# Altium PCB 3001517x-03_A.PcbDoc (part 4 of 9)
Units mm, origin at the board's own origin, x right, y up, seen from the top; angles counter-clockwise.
Board outline 100 x 72 mm, 10 copper layers (Top, GND_2, Signal_3, Signal_4, PWR_5, GND_6, Signal_7, Signal_8, GND_9, Bottom), stack 1.6 mm thick; 602 components, 497 nets, 2372 pads, 1602 vias.
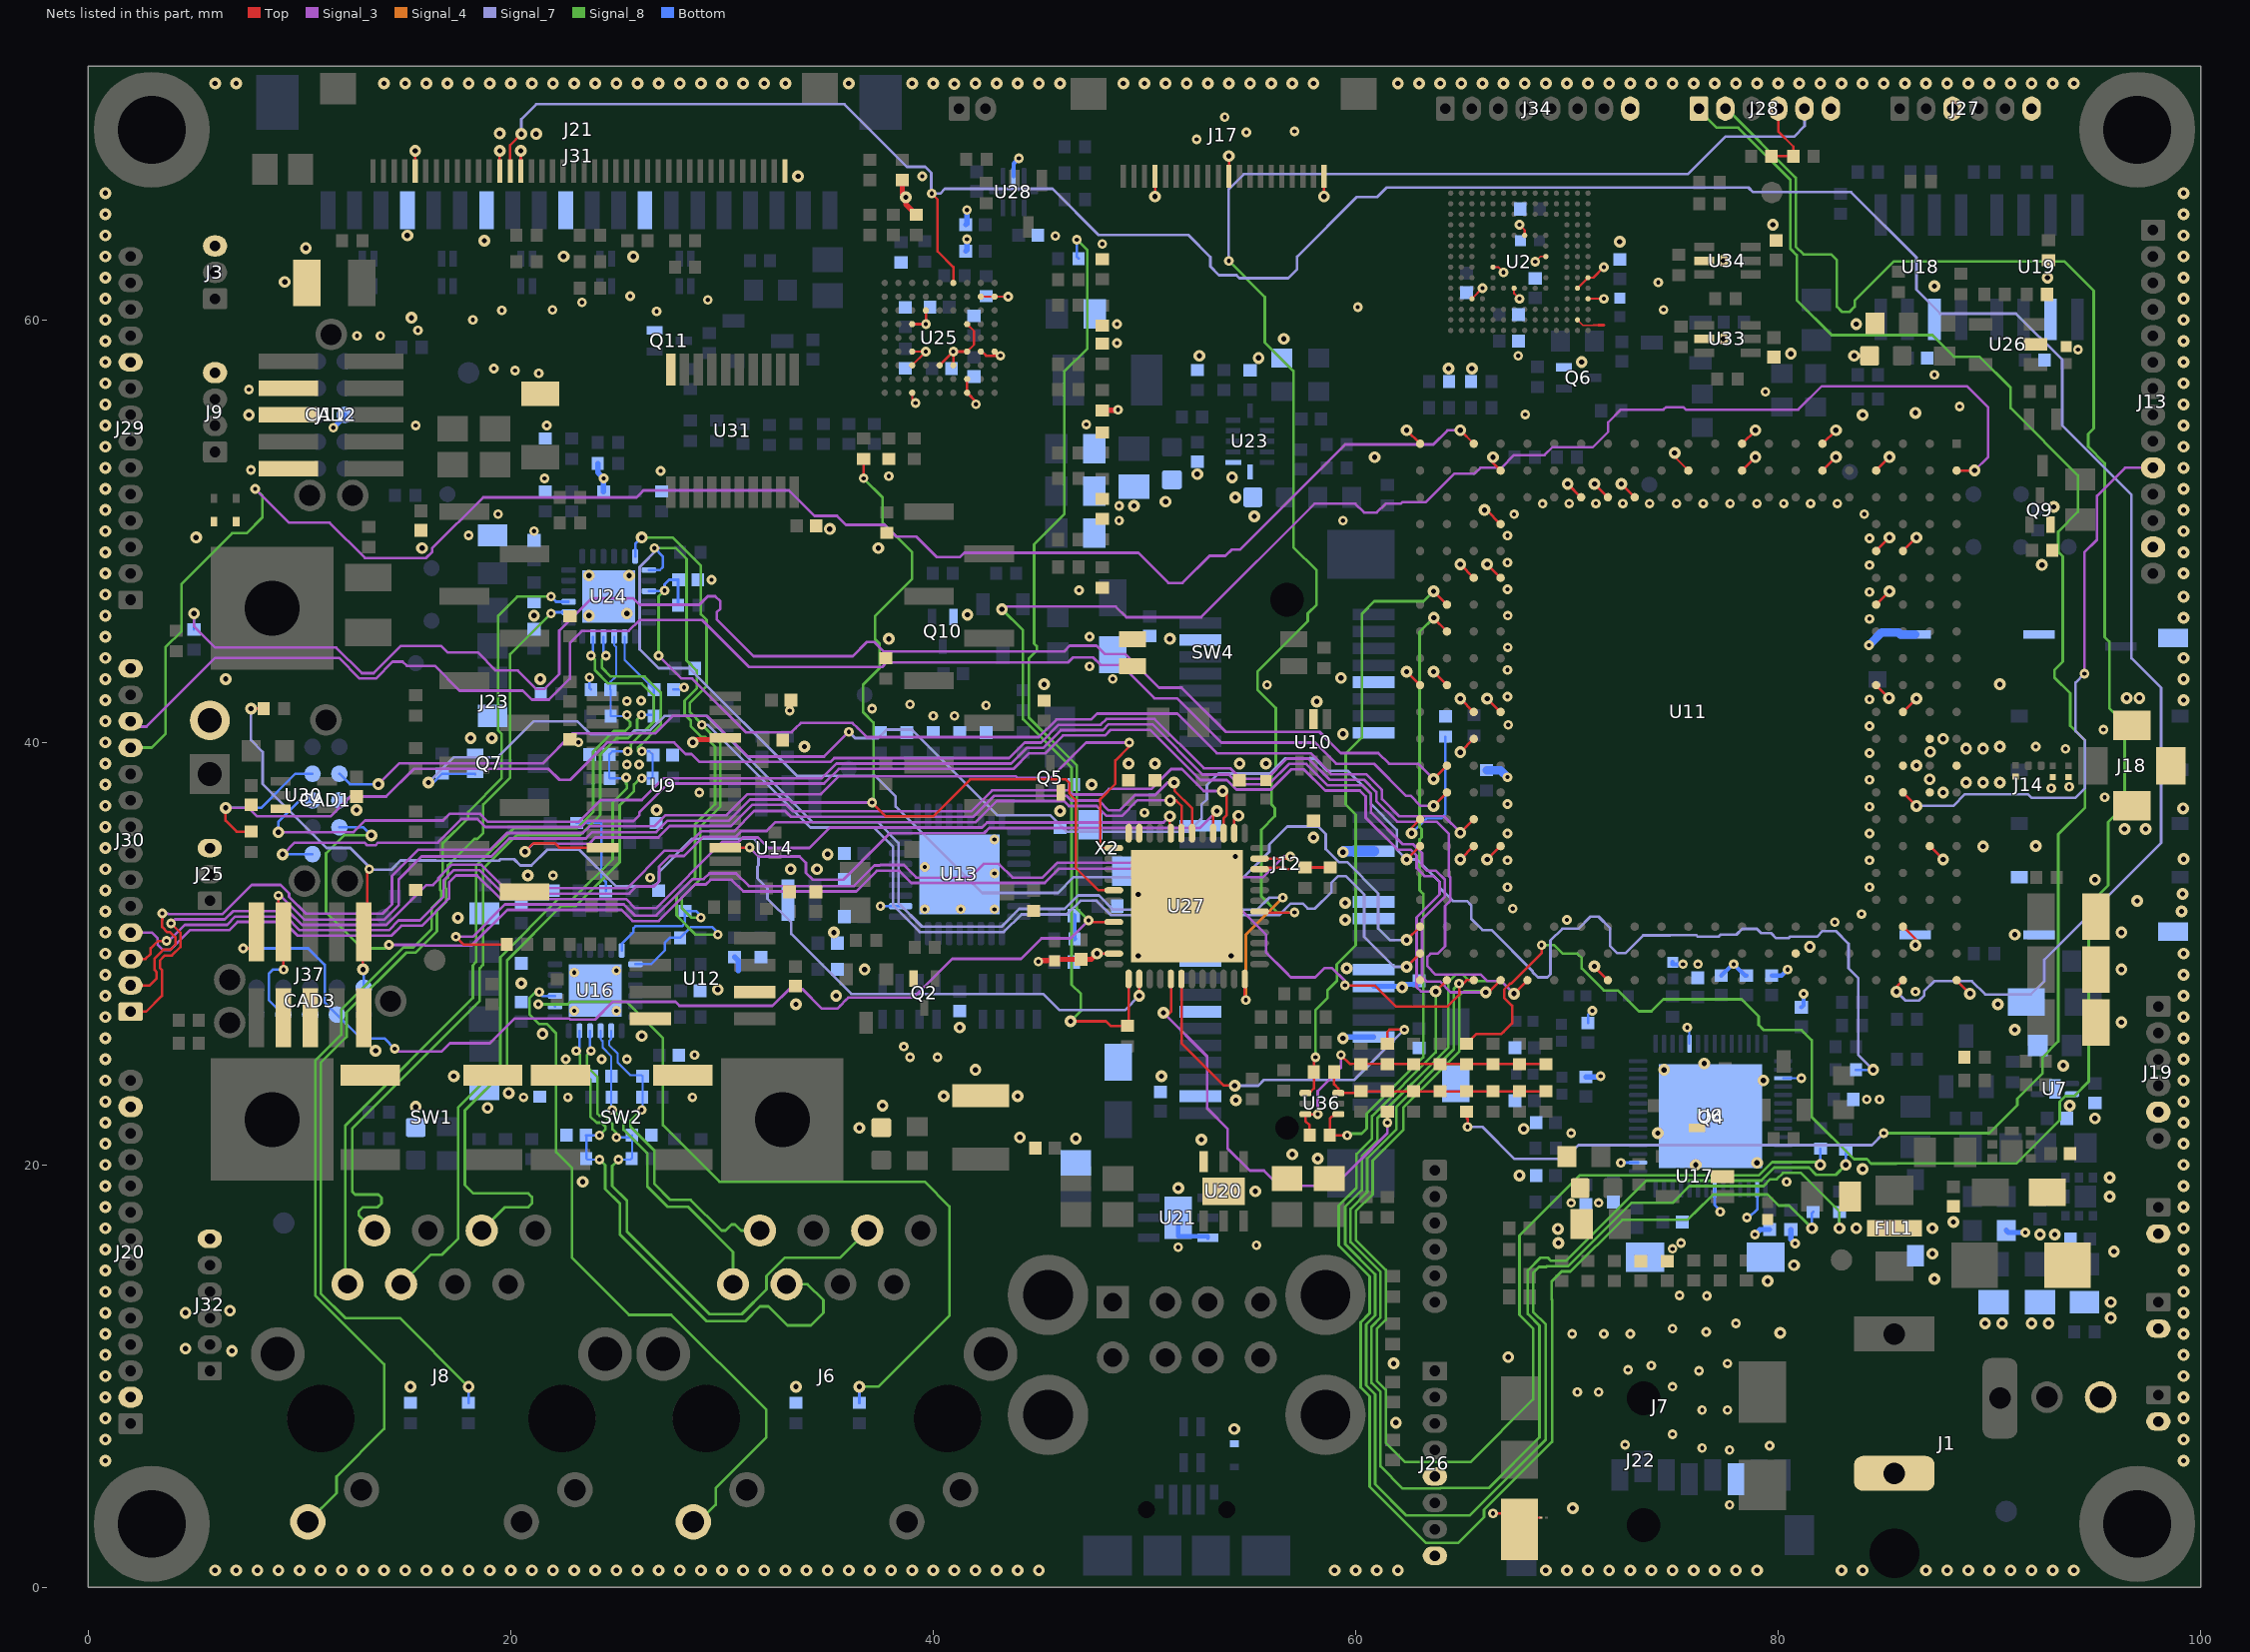
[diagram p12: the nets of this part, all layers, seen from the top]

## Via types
v1: diameter 0.56, hole 0.25, Top to Bottom, tented both sides, 1002 vias
v2: diameter 0.46, hole 0.2, Top to Bottom, tented both sides, 468 vias
v3: diameter 0.457, hole 0.2, Top to Bottom, tented both sides, 132 vias

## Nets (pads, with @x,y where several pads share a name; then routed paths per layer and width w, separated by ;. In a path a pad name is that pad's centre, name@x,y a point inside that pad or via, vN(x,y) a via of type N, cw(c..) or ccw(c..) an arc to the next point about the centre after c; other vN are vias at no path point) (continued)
ENET_MDC: R50.2 U11.AA19 U16.13 U24.13 | length 82.7
  Top w0.119: v1(62.415,30.645) U11.AA19@63.05,31.28
  Signal_8 w0.127: v2(26.8,49.2) 27.8,49.2 28.32,48.68 28.32,43.88 28.8,43.4 28.8,42.554 28.225,41.979 28.225,41.317 28.525,41.018 28.525,40.755 29.03,40.25 29.215,40.25 29.67,39.795 29.67,37.076 28.72,36.126 28.72,33.634 27.846,32.759 27.846,31.809 28.755,30.9 29.9,30.9 v2(29.8,30.9)
  Signal_7 w0.127: v2(26.8,49.2) 27,49.2 26.1,48.3 26.1,44.405 26.995,43.51 28.447,43.51 33.535,38.422 37.243,38.422 38.221,37.445 38.221,36.966 42.315,32.872 43.285,32.872 43.287,32.874 45.902,32.874 46.649,33.621 54.705,33.621 55.908,34.824 55.908,35.158 56.768,36.017 58.223,36.017 58.585,35.656 58.585,34.95 59.205,34.329 59.589,34.329 61.067,32.851 61.067,31.19 61.613,30.645 v1(62.415,30.645)
  Bottom w0.119: U16.13@25.9,29.5 26.633,29.5 27.3,30.167 27.3,30.529 27.521,30.75 R50.2@28.02,30.75 28.52,31.25 29.55,31.25 29.9,30.9 v2(29.8,30.9) ; U24.13@26.539,48.157 27.057,48.157 27.195,48.295 27.195,48.805 v2(26.8,49.2)
ENET_MDIO: R49.2 U11.AA20 U16.12 U24.12 | length 73.8
  Top w0.119: v1(62.415,29.375) U11.AA20@63.05,30.01
  Signal_8 w0.127: v1(26.2,49.7) 27.659,49.7 29,48.359 29,46.069 29.27,45.798 29.27,42.665 28.479,41.874 28.479,41.423 29.043,40.859 v2(29.043,40.831) 29.924,39.95 29.924,36.971 28.974,36.021 28.974,33.528 28.1,32.654 28.1,32.15 28.55,31.7 v2(29,31.7)
  Signal_7 w0.127: v2(29.043,40.831) 29.323,40.831 34.183,35.97 37.179,35.97 38.1,35.05 38.1,32.287 39.362,31.024 43.341,31.024 44.177,31.86 46.322,31.86 46.965,32.503 47.735,32.503 48.417,31.822 56.377,31.822 56.926,32.37 57.487,32.37 57.726,32.131 58.074,32.131 58.85,32.907 58.85,33.345 59.176,33.67 59.529,33.67 60.4,32.8 60.4,30.8 61.825,29.375 v1(62.415,29.375)
  Bottom w0.119: U16.12@25.25,30.15 25.25,30.465 25.808,31.024 25.808,31.208 25.9,31.3 28.1,31.3 28.25,31.45 R49.2@28.25,32.02 28.78,32.02 29,31.8 v2(29,31.7) ; U24.12@25.889,48.807 25.889,49.389 v1(26.2,49.7)
ENET_PWR/IO26: Q7.G R51.2 U27.36 | length 58.2
  Top w0.119: U27.36@54.75,28.8 54.75,27.85 v2(54.8,27.8)
  Signal_4 w0.127: v2(54.8,27.8) 54.8,30.9 v3(56.55,32.65)
  Signal_7 w0.127: v1(16.1,38.1) 17.3,39.3 19.391,39.3 21.091,41 23.154,41 23.773,40.381 25.674,40.381 25.863,40.57 26.6,40.57 27.281,41.252 29.261,41.252 34.289,36.224 37.376,36.224 38.354,35.246 38.354,32.392 39.468,31.278 43.236,31.278 44.072,32.114 46.217,32.114 46.86,32.757 47.84,32.757 48.522,32.076 55.326,32.076 55.9,32.65 v3(56.55,32.65)
  Bottom w0.119: v1(16.1,38.1) 16.33,38.1 R51.2@16.75,38.52 18.29,38.52 Q7.G@18.31,38.5
ETH1_LED1/#REGOFF: J6.9 U16.3 | length 33.8
  Signal_8 w0.125: v2(21.344,28.187) 21.187,28.187 20.88,27.88 20.88,27.12 21.33,26.67 21.694,26.67 22.144,26.22 22.144,20.606 22.9,19.85 22.9,15.6 25.6,12.9 27.6,12.9 32.1,8.4 32.1,7.1 29.7,4.7 29.7,3.909 28.89,3.1 J6.9@28.64,3.1
  Bottom w0.125: v2(21.344,28.187) 21.344,28.156 21.5,28 U16.3@22.1,28
ETH1_LED2/#NINTSEL: R52.1 U16.2 | length 38.4
  Signal_8 w0.125: v2(21.3,27.6) 22.707,27.6 22.826,27.72 25.48,27.72 27.2,26 27.2,21.873 29.873,19.2 39.6,19.2 40.763,18.037 40.763,12.863 37.4,9.5 v1(36.5,9.5)
  Bottom w0.125: v2(21.3,27.6) 22,27.6 U16.2@22.1,27.5 ; R52.1@36.5,8.73 v1(36.5,9.5)
ETH1_RX_N: C33.1 J6.6 R47.1 U16.22 | length 27.2
  Signal_8 w0.127: v3(23.8,25.4) 23.6,25.2 23.6,24.667 24.1,24.167 24.1,22.43 24.2,22.33 24.422,22.33 24.815,21.937 24.815,21.685 25,21.5 v3(25,21.3) ; v3(25.1,20.25) 24.8,19.95 24.8,19 25.497,18.303 25.497,16.838 29.401,12.933 30.933,12.933 32.107,14.107 32.107,14.745 32.963,15.6 35.58,15.6 J6.6@36.87,16.89
  Bottom w0.102: U16.22@23.75,26.35 23.75,25.45 v3(23.8,25.4) ; v3(25,21.3) 25.64,21.3 C33.1@25.74,21.4 25.74,20.32 R47.1@25.72,20.3 25.67,20.25 v3(25.1,20.25)
ETH1_RX_P: C32.1 J6.3 R46.1 U16.23 | length 27.1
  Signal_8 w0.127: v3(23.1,25.4) 23.27,25.23 23.27,24.53 23.77,24.03 23.77,22.293 24.063,22 24.285,22 24.485,21.8 24.485,21.685 v3(24.2,21.4) ; v3(24.2,20.25) 24.47,19.98 24.47,18.863 25.167,18.167 25.167,16.701 29.264,12.603 31.103,12.603 31.8,13.3 32.2,13.3 33.1,12.4 34.2,12.4 34.8,13 34.8,13.6 34.05,14.35 J6.3@33.06,14.35
  Bottom w0.102: v3(23.1,25.4) 23.25,25.55 U16.23@23.25,26.35 ; v3(24.2,20.25) 23.63,20.25 R46.1@23.58,20.3 23.58,21.38 C32.1@23.56,21.4 v3(24.2,21.4)
ETH1_TX_N: C31.1 J6.2 R45.1 U16.20 | length 15.1
  Signal_8 w0.127: v3(26.2,22.6) 26.165,22.6 25.665,22.1 25.665,21.8 26.8,20.665 26.8,19.1 27.554,18.346 28.521,18.346 29.977,16.89 30.165,16.89 30.45,17.175 30.615,17.175 30.9,16.89 J6.2@31.79,16.89
  Bottom w0.102: U16.20@24.75,26.35 24.75,25.954 24.653,25.857 24.653,25.679 25.065,25.266 25.065,24.835 25.649,24.251 26.189,24.251 C31.1@26.24,24.2 26.24,22.64 v3(26.2,22.6)
ETH1_TX_P: C30.1 J6.1 R44.1 U16.21 | length 15.2
  Signal_8 w0.127: v3(24.8,22.6) 24.835,22.6 25.335,22.1 25.335,21.663 26.47,20.528 26.47,18.963 27.417,18.016 28.384,18.016 30.52,15.88 J6.1@30.52,14.35
  Bottom w0.102: U16.21@24.25,26.35 24.25,25.954 24.348,25.856 24.348,25.552 24.76,25.14 C30.1@24.76,24.2 24.76,22.64 v3(24.8,22.6)
ETH2_LED1/#REGOFF: J8.9 U24.3 | length 53.6
  Signal_8 w0.125: J8.9@10.39,3.1 11.75,4.46 11.75,5.25 14,7.5 14,10.558 10.741,13.817 10.741,24.929 11.973,26.162 11.973,27.345 14.928,30.3 15.391,30.3 16.248,31.157 16.248,32.133 16.695,32.58 16.695,32.969 16.648,33.016 16.648,33.584 16.769,33.705 16.769,35.203 17.982,36.415 17.982,36.712 19.57,38.3 19.57,40.394 19.4,40.564 19.4,46 20.3,46.9 v2(21.9,46.9)
  Bottom w0.125: v2(21.9,46.9) 22.143,46.657 U24.3@22.739,46.657
ETH2_LED2/#NINTSEL: R124.1 U24.2 | length 47.5
  Signal_8 w0.125: v1(18,9.5) 14.75,12.75 12.164,12.75 11,13.914 11,24.832 12.225,26.057 12.225,27.225 15.048,30.048 15.496,30.048 16.5,31.052 16.5,32.029 16.947,32.476 16.947,33.073 16.9,33.12 16.9,33.48 17.021,33.601 17.021,34.179 18.273,35.43 18.419,35.43 18.695,35.706 18.695,37.069 19.972,38.346 19.972,44.172 v2(21.9,46.1)
  Bottom w0.125: R124.1@18,8.73 v1(18,9.5) ; v2(21.9,46.1) 21.957,46.157 U24.2@22.739,46.157
ETH2_RST: C19.2 R90.2 U11.W15 U24.15 | length 50.1
  Top w0.125: v1(64.955,35.725) U11.W15@65.59,36.36
  Signal_3 w0.125: v2(27,44.1) 28.08,43.019 28.581,43.019 31.124,40.476 33.283,40.476 33.48,40.674 33.726,40.919 36.174,40.919 36.419,40.674 36.846,40.247 44.994,40.247 45.836,41.089 47.482,41.089 47.754,41.361 51.553,41.361 53.428,39.486 57.865,39.486 58.869,38.482 60.51,38.482 61.232,37.76 61.232,37.748 61.244,37.748 61.246,37.746 61.246,37.315 62.058,36.503 64.177,36.503 v1(64.955,35.725)
  Signal_8 w0.125: v2(27,44.1) 27,46.908 v3(27.284,47.192)
  Bottom w0.125: U24.15@26.539,47.157 27.249,47.157 v3(27.284,47.192) 27.284,47.484 27.5,47.7 C19.2@27.94,47.7 27.92,47.68 R90.2@27.92,46.5
ETH2_RX_N: C51.1 J8.6 R88.1 U24.22 | length 40.3
  Signal_8 w0.127: J8.6@18.62,16.89 19.73,18 20.825,18 21,18.175 21,18.475 20.825,18.65 18.23,18.65 17.83,19.05 17.83,22.58 19.83,24.58 19.83,29.694 22.39,32.254 23.079,32.254 25.152,34.327 25.152,37.023 25.83,37.701 25.83,38 26.13,38.3 v2(26.2,38.3) ; v2(24.5,44.1) 24.315,43.915 24.315,43.544 24.739,43.12 26.337,43.12 27.1,42.357 27.1,40.835 26.028,39.763 26.028,39.577 v2(26.201,39.577)
  Bottom w0.102: U24.22@24.389,45.007 24.389,44.211 v2(24.5,44.1) ; v2(26.2,38.3) R88.1@26.72,38.3 26.72,39.42 26.563,39.577 v2(26.201,39.577)
ETH2_RX_P: C50.1 J8.3 R87.1 U24.23 | length 40.2
  Signal_8 w0.127: J8.3@14.81,14.35 16.21,15.75 16.75,15.75 17.5,16.5 17.5,22.717 19.5,24.717 19.5,29.831 22.253,32.584 22.942,32.584 24.822,34.464 24.822,37.16 25.5,37.837 25.5,38 25.464,38.036 v2(25.464,38.336) ; v2(23.8,44.1) 23.985,43.915 23.985,43.408 24.603,42.79 26.2,42.79 26.77,42.22 26.77,40.972 25.685,39.887 25.685,39.585 25.677,39.577 v2(25.532,39.577)
  Bottom w0.102: v2(23.8,44.1) 23.889,44.189 U24.23@23.889,45.007 ; v2(25.464,38.336) 25.428,38.3 R87.1@24.68,38.3 24.66,38.32 C50.1@24.66,39.425 24.812,39.577 v2(25.532,39.577)
ETH2_TX_N: C49.1 J8.2 R86.1 U24.20 | length 39.5
  Signal_8 w0.127: J8.2@13.54,16.89 12.8,17.63 12.8,17.8 13,18 13.7,18 13.875,18.175 13.875,18.45 13.725,18.6 12.625,18.6 12.5,18.725 12.5,21.733 18.53,27.763 18.53,29.312 18.683,29.465 18.683,34.016 20.267,35.6 23.267,35.6 24.23,36.563 24.23,39.425 25.005,40.2 25.55,40.2 25.98,40.63 25.98,41.08 25.995,41.095 25.995,41.105 v3(26.19,41.3)
  Bottom w0.102: U24.20@25.389,45.007 25.389,43.901 C49.1@26.79,42.5 26.77,42.48 R86.1@26.77,41.25 26.72,41.3 v3(26.19,41.3)
ETH2_TX_P: C48.1 J8.1 R85.1 U24.21 | length 39.6
  Signal_8 w0.127: J8.1@12.27,14.35 12.17,14.45 12.17,21.87 18.2,27.9 18.2,29.448 18.353,29.601 18.353,34.153 20.13,35.93 23.13,35.93 23.9,36.7 23.9,39.562 24.868,40.53 25.413,40.53 25.65,40.767 25.65,40.95 25.5,41.1 v3(25.5,41.3)
  Bottom w0.102: U24.21@24.889,45.007 24.889,44.611 24.987,44.513 24.987,43.138 24.71,42.861 C48.1@24.71,42.5 24.73,42.48 R85.1@24.73,41.25 25.45,41.25 v3(25.5,41.3) 25.42,41.3 v3@25.46,41.34
EXP_GPIO_1: J30.11 U11.W1 | length 81.7
  Top w0.119: v1(64.955,54.775) U11.W1@65.59,54.14
  Signal_3 w0.127: v2(7.9,52) 9.5,50.4 11.428,50.4 13.098,48.73 15.995,48.73 16.27,49.005 16.27,49.177 18.695,51.602 21.252,51.602 21.254,51.6 25.951,51.6 26.239,51.888 26.281,51.93 33.172,51.93 34.38,50.722 35.443,50.722 35.865,50.3 37.7,50.3 38.258,49.742 39.192,49.742 40.155,48.78 41.27,48.78 41.465,48.974 49.711,48.974 51.139,47.547 51.805,47.547 53.085,48.827 53.833,48.827 54.126,49.12 54.52,49.12 59.5,54.1 63.675,54.1 64.35,54.775 v1(64.955,54.775)
  Signal_8 w0.127: J30.11@2,39.75 3,39.75 3.65,40.4 3.65,44.5 4.412,45.262 4.412,47.5 6.812,49.9 7.5,49.9 8.241,50.641 8.241,51.659 v2(7.9,52)
EXP_GPIO_2: J30.12 U11.Y14 | length 72
  Top w0.119: v1(63.685,36.995) U11.Y14@64.32,37.63
  Signal_3 w0.127: J30.12@2,40.75 2.75,40.75 6,44 11.865,44 12.842,43.023 13.61,43.023 14.406,43.819 14.878,43.819 15.074,43.623 16.399,43.623 17.569,42.453 20.563,42.453 20.995,42.022 21.805,42.022 22.8,43.016 22.8,44.7 23.375,45.276 25.586,45.276 26.101,45.791 29.067,45.791 31.285,43.572 37.586,43.572 37.804,43.791 46.394,43.791 46.624,44.02 47.574,44.02 47.922,43.672 48.885,43.672 50.471,42.086 50.716,42.086 50.718,42.084 51.544,42.084 53.637,39.991 58.074,39.991 59.078,38.987 60.864,38.987 62.373,37.477 62.599,37.477 63.08,36.995 v1(63.685,36.995)
EXP_GPIO_3: R253.2 U11.Y13 | length 71.6
  Top w0.119: v1(63.685,38.265) U11.Y13@64.32,38.9
  Signal_3 w0.127: v1(5,46.1) 5,45.5 6.008,44.492 11.732,44.492 12.947,43.277 13.504,43.277 14.798,44.57 16.695,44.57 17.006,44.259 18.44,44.259 19.3,43.4 20.335,43.4 21.205,42.53 21.595,42.53 22.292,43.227 22.292,45.292 23.824,46.824 25.8,46.824 26.106,46.519 28.924,46.519 29.326,46.921 29.674,46.921 29.92,46.674 29.92,46.326 29.751,46.156 29.751,45.826 31.496,44.08 36.186,44.08 36.858,44.752 37.206,44.752 37.66,44.299 46.184,44.299 46.464,44.579 47.734,44.579 48.132,44.18 49.096,44.18 50.682,42.594 50.926,42.594 50.929,42.592 51.755,42.592 53.848,40.499 58.285,40.499 59.289,39.495 61.074,39.495 61.579,38.99 62.961,38.99 v1(63.685,38.265)
  Bottom w0.119: R253.2@5,45.345 v1(5,46.1)
EXP_I2C_GPIO/IO32: J28.5 U27.42 | length 70
  Top w0.119: U27.42@55.45,32 55.5,31.95 v2(57.1,31.95)
  Signal_8 w0.127: v2(53.991,62.795) 55.7,61.086 55.7,58.924 57.05,57.574 57.05,49.233 58.146,48.137 58.146,46.513 57.733,46.1 57.733,45.741 55.35,43.358 55.35,42.5 56.22,41.63 56.22,38.714 56.018,38.511 56.018,37.048 56.17,36.895 56.17,36.505 55.528,35.862 55.528,32.72 56.298,31.95 v2(57.1,31.95)
  Signal_7 w0.127: v2(53.991,62.795) 53.991,66.191 54.7,66.9 75.725,66.9 77.5,68.675 80.75,68.675 81.25,69.175 J28.5@81.25,70
EXP_I2C_IRQ_N: J28.4 R117.2 R271.2 | length 3.6
  Top w0.119: R271.2@79.68,67.75 R117.2@80.72,67.75 80.72,68.205 80,68.925 J28.4@80,70
EXP_I2C_SCL: J28.1 R106.2 | length 89.8
  Top w0.119: R106.2@65.25,22.52 65.4,22.37 65.25,22.22 65.3,22.17 v2(65.3,21.8)
  Signal_8 w0.127: J28.1@76.25,70 76.25,69.95 77.1,69.1 78.109,69.1 80.578,66.631 80.578,63.362 80.878,63.062 80.878,60.94 82.54,59.278 87.299,59.278 88.32,58.258 89.537,58.258 91.008,56.787 91.008,56.167 91.007,56.166 91.007,55.823 94.191,52.639 94.191,50.904 93.262,49.975 93.262,49.009 93.471,48.8 93.471,43.816 93.079,43.424 93.079,43.076 93.825,42.33 93.825,40.787 94.528,40.085 94.528,36.921 93.26,35.652 93.26,25.843 92.522,25.105 92.522,24.332 91.321,23.131 91.321,22.826 89.995,21.5 v2(85,21.5)
  Signal_7 w0.127: v2(65.3,21.8) 66,21.8 67.521,20.279 69.879,20.279 70.54,20.94 84.44,20.94 v2(85,21.5)
EXP_I2C_SDA: J28.2 R107.2 | length 107.9
  Top w0.119: R107.2@65.25,25.73 65.725,26.205 66.888,26.205 66.894,26.199 66.996,26.3 67,26.3 67.4,26.7 67.4,27.536 67.025,27.911 67.025,28.299 67.301,28.575 67.358,28.575 68.8,30.016 v2(68.8,30.4)
  Signal_8 w0.127: v2(68.8,30.4) 69.4,30.4 69.8,30 70.5,30 70.7,29.8 70.7,29.3 71.746,28.254 72.421,28.254 73.4,27.276 74,27.276 74.563,27.838 78.273,27.838 79.079,27.032 79.079,26.626 79.326,26.379 81.115,26.379 81.593,25.902 81.593,22.273 83.595,20.271 84.198,20.271 84.405,20.063 85.595,20.063 85.602,20.07 91.273,20.07 93.33,22.127 93.33,22.995 93.605,23.27 93.995,23.27 94.008,23.258 94.7,23.95 94.7,32.302 95.625,33.227 95.625,36.222 96.408,37.005 96.408,40.905 95.682,41.63 95.682,44.762 95.461,44.984 95.461,53.215 94.676,54 94.676,54.6 94.942,54.866 94.942,61.375 93.542,62.774 85.475,62.774 83.621,60.921 83.621,60.626 83.374,60.38 83.026,60.38 82.78,60.626 82.78,62.82 82.5,63.1 81.2,63.1 80.832,63.468 80.832,66.736 77.568,70 J28.2@77.5,70
GND: C1.2 C2.1 C3.1 C4.1 C5.1 C6.1 C7.1 C8.1 C9.2 C10.1 C11.1 C12.1 C13.1 C14.1 C15.1 C16.1 C17.2 C18.1 C19.1 C21.1 C22.1 C25.1 C27.1 C28.2 C29.1 C30.2 C31.2 C32.2 C33.2 C34.2 C35.2 C36.2 C37.1 C38.1 C39.1 C40.1 C41.1 C42.1 C43.1 C44.1 C45.2 C46.2 C47.1 C48.2 C49.2 C50.2 C51.2 C52.1 C53.1 C54.1 C56.1 C57.1 C58.1 C59.1 C60.2 C61.1 C62.1 C63.2 C64.2 C65.2 C66.1 C67.1 C68.1 C69.1 C70.1 C71.1 C72.1 C73.1 C74.1 C75.1 C76.1 C77.1 C78.1 C79.1 C80.1 C81.2 C82.2 C83.2 C84.2 C85.2 C86.1 C87.2 C89.2 C90.1 C91.1 C92.2 C93.2 C94.2 C95.1 C96.2 C97.1 C98.1 C99.1 C100.1 C101.1 C102.2 C103.2 C104.1 C105.1 C106.1 C109.1 C110.1 C111.1 C112.1 C113.1 C114.1 C115.1 C116.1 C117.1 C118.1 C119.1 C120.1 C122.1 C124.1 C125.1 C126.1 C127.1 C128.1 C129.1 C130.1 C131.2 C134.2 C137.2 C138.2 C139.2 C140.2 C143.2 C144.1 C145.1 C146.1 C150.1 C151.2 C152.1 C153.1 C155.1 C156.1 C157.1 CAD1.3 CAD2.3 CAD3.3 D1.K D2.A D3.K D4.K D6.1 D7.1 D10.1 D12.K FIL1.2 J1.2 J2.2 J3.3 J4.2 J5.2 J7.6 J7.9 J7.10 J9.4 J10.2 J11.3 J11.5 J11.9 J12.4 J12.9 J12.15 J12.18 J12.21 J12.26 J12.27 J12.29 J12.34 J12.35 J12.37 J12.40 J12.43 J12.50 J13.13 J14.5 J14.11 J14.12 J14.13 J14.14 J14.15 J14.16 J17.1 J17.10 J17.17 J18.2 J18.3 J18.4 J19.5 J20.2 J20.13 J21.1 J21.26 J21.28 J21.36 J22.1 J23.10 J25.3 J26.5 J26.8 J27.3 J27.6 J28.6 J29.10 J30.14 J31.4 J31.7 J31.10 J31.13 J32.6 J34.8 J35.2 J37.3 J37.5 J37.9 L12.1 L13.1 L15.1 NT1.2 Q2.S Q4.S Q5.S Q6.S Q7.S Q9.S Q10.S Q11.S R5.1 R14.1 R28.2 R29.2 R37.1 R38.2 R43.2 R54.1 R55.1 R60.2 R61.2 R62.2 R63.2 R70.1 R71.1 R73.1 R74.1 R76.2 R84.1 R92.1 R112.1 R113.1 R130.2 R134.2 R136.2 R138.1 R144.1 R145.1 R146.1 R147.1 R153.1 R156.1 R157.1 R162.2 R163.2 R164.2 R165.2 R166.1 R174.1 R175.1 R176.1 R177.1 R178.1 R180.1 R184.1 R212.1 R226.1 R238.1 R239.1 R267.2 SW1.1 SW1.2 SW2.1 SW2.2 SW4.1 SW4.2 U2.C4 U2.E7 U2.G5 U2.H10 U2.K8 U2.N2 U2.N5 U2.P4 U2.P6 U5.A U6.3 U6.16 U6.21 U6.30 U6.47 U6.57 U7.2 U7.5 U9.25 U10.2 U11.A13 U11.A21 U11.AA1 U11.AA10 U11.AA21 U11.B12 U11.B14 U11.B16 U11.C5 U11.C11 U11.C13 U11.C19 U11.D2 U11.D5 U11.D7 U11.D10 U11.F1 U11.F2 U11.G20 U11.J1 U11.J2 U11.L2 U11.N3 U11.P3 U11.P21 U11.R3 U11.V2 U11.V4 U11.V6 U11.V11 U11.V16 U11.W6 U11.W11 U11.W12 U11.W16 U11.Y10 U12.4 U12.6 U13.11 U13.37 U14.6 U16.25 U17.2 U18.2 U19.2 U20.3 U20.7 U21.3 U21.7 U23.1 U23.12 U24.25 U25.C1 U25.C3 U25.C4 U25.C6 U25.D7 U25.E3 U25.F3 U25.G1 U25.G2 U25.G4 U25.G6 U25.H4 U25.H8 U25.J4 U25.J8 U26.2 U27.2 U27.11 U27.12 U27.23 U27.49 U28.2 U30.3 U31.10 U33.2 U34.2 X2.2 X2.4 | length 98.9
  Top w0.076: v2(68.5,62.75) 68.75,63 U2.K8@69,63 ; U2.N2@70.5,60 70.75,59.75 71.25,59.75
  Top w0.1: U25.C1@39,56.55 39,56.225 v2(39.162,56.062) ; U25.C3@39,57.85 v2(39.65,58.5) U25.C4@39,58.5 ; U25.G4@41.6,58.5 41.925,58.825 41.925,59.475 U25.G6@41.6,59.8 ; U25.H8@42.25,61.1 U25.J8@42.9,61.1 v2(43.55,61.1) ; U2.C4@65.5,61 v2(66,61.5) ; U2.E7@66.5,62.5 66.75,62.5 v2(67,62.25) ; U2.G5@67.5,61.5 67.5,61.25 v2(67.75,61) ; J22.1@67.75,2.75 68.3,3.3 NT1.2@68.773,3.3 ; v2(67.75,64.5) 68,64.25 U2.H10@68,64 ; U2.N5@70.5,61.5 U2.P6@71,62 71.25,62 v2(71.75,62.5) ; U2.P4@71,61 v2(71.75,61) ; 71.25,59.75 71.5,59.75 ; v1(75.1,53.7) 75.1,53.52 U11.L2@75.75,52.87
  Top w0.125: J21.36@15.476,67.05 v1(15.476,68.007) ; J21.28@19.476,67.05 v1(19.476,68.007) ; J21.26@20.476,67.05 v1(20.476,68.007) ; U25.C6@39,59.8 v3(39.65,59.8) U25.D7@39.65,60.45 ; U25.E3@40.325,57.875 v3(40.95,58.5) ; U25.F3@40.945,57.902 40.95,57.907 v3(40.95,58.5) ; U25.G2@41.6,57.2 U25.G1@41.6,56.55 42.027,56.123 v2(42.027,56.002) ; U25.G4@41.6,58.5 v3(40.95,58.5) ; U25.H4@42.3,58.5 42.495,58.305 v2(43.175,58.305) ; v1(47.75,30) U27.23@48.55,30 ; v1(50.5,65.843) J17.17@50.5,66.8 ; J17.10@54,66.8 v1(54,67.757) ; U27.2@54.25,35.7 54.25,36.325 v1(54.45,36.525) ; v1(58.5,65.843) J17.1@58.5,66.8 ; v1(62.415,43.345) U11.AA10@63.05,42.71 ; v1(62.415,54.775) U11.AA1@63.05,54.14 ; v1(63.685,43.345) U11.Y10@64.32,42.71 ; v1(64.955,34.455) U11.W16@65.59,35.09 ; v1(64.955,39.535) U11.W12@65.59,40.17 ; v1(64.955,42.075) U11.W11@65.59,41.44 ; v1(64.955,48.425) U11.W6@65.59,47.79 ; v1(66.1,51) 66.19,51 U11.V4@66.86,50.33 ; v1(66.225,34.455) U11.V16@66.86,35.09 ; v1(66.225,42.075) U11.V11@66.86,41.44 ; v1(66.225,48.425) U11.V6@66.86,47.79 ; v2(66.5,3.5) J22.1@67,3.5 ; v1(66.5,53.5) 66.5,53.23 U11.V2@66.86,52.87 ; v1(70.035,52.235) U11.R3@70.67,51.6 ; v1(71.3,29.4) 71.3,29.38 U11.P21@71.94,28.74 ; v1(71.305,52.235) U11.P3@71.94,51.6 ; 71.5,59.75 71.75,59.75 ; v1(72.575,52.235) U11.N3@73.21,51.6 ; U11.J2@78.29,52.87 v1(78.925,53.505) ; U11.J1@78.29,54.14 v1(78.925,54.775) ; U11.F2@82.1,52.87 v1(82.735,53.505) ; U11.F1@82.1,54.14 v1(82.735,54.775) ; U11.D10@84.64,42.71 v1(85.25,42.1) ; U11.D7@84.64,46.52 v1(85.275,47.155) ; U11.D5@84.64,49.06 v1(85.275,49.695) ; U11.D2@84.64,52.87 v1(85.275,53.505) ; U11.C19@85.91,31.28 86.5,30.69 v1(86.5,30.4) ; U11.C11@85.91,41.44 v1(86.545,42.075) ; U11.C5@85.91,49.06 v1(86.545,49.695) ; U11.B16@87.18,35.09 v1(87.815,34.455) ; U11.A21@88.45,28.74 v1(89.085,28.105)
  Top w0.25: v1(28.614,40) 28.614,40.058 28.536,40.136 30.061,40.136 U9.25@30.15,40.225 ; R176.1@38.534,66.62 38.534,65.966 v1(38.7,65.8) 38.7,65.48 R177.1@39.2,64.98 ; v2(44.977,29.626) 45.019,29.668 C120.1@45.75,29.668 45.814,29.732 C105.1@47,29.732 47.482,29.732 v1(47.75,30) ; R113.1@48,55.72 48.72,55.72 v2(48.75,55.75)
  Bottom w0.1: v3(75.7,26.5) 75.8,26.5 U6.47@75.8,25.74 ; U6.3@80.23,24.11 80.23,24.1 v3(81.1,24.1)
  Bottom w0.125: R62.2@23.123,36.189 23.134,36.2 24.295,36.2 24.295,33.605 24.5,33.4 C28.2@24.5,32.96 ; v3(23.725,43.075) 23.725,42.575 C48.2@23.8,42.5 ; C49.2@27.71,42.5 v2@28.2,42.5 ; v2(37.5,32.25) U13.11@38.45,32.25 ; C134.2@71,26.71 71,27.1 v2(71.2,27.3) ; v3(72.55,20.1) 72.56,20.11 U6.30@73.37,20.11 ; U6.21@77,18.88 77,18.1 77.3,17.8 77.276,17.776 v2(77.254,17.776) ; v2(78.524,17.513) 78.613,17.513 79.02,17.92 79.02,18.86 U6.16@79,18.88
  Bottom w0.2: U28.2@43.8,66.8 43.8,67.4 v2(44.05,67.65) ; U21.7@51.6,17.5 51.6,16.625 53,16.625 U21.3@53,16.55 ; C131.2@75,29.6 75,29.5 v2(75.5,29.5) ; C97.1@77.3,28.96 77.84,29.5 v2(77.9,29.5) 78.44,28.96 C93.2@78.5,28.96 ; C94.2@79.7,28.96 80.16,28.96 v2(80.45,29.25) ; C89.2@81.1,27.46 81.2,27.56 v2(81.2,28.1)
  Bottom w0.25: v2(11.6,54.9) 12.135,55.435 CAD2.3@12.135,55.5 ; R162.2@24.12,53.2 24.12,52.78 v2(24.4,52.5) 24.389,52.489 C46.2@24.389,51.867 ; C68.1@30.6,29.84 30.775,29.665 30.775,29.2 ; C144.1@41.54,63.25 41.6,63.31 v2(41.6,63.815) ; C145.1@41.54,64.5 41.6,64.56 v2(41.6,65.2) ; C79.1@46.66,31.8 46.66,30.72 R70.1@46.68,30.7 ; v1(59.4,26) 59.4,26.05 J12.43@60.85,26.05 ; J12.37@60.85,28.45 62.15,28.45 v1(62.2,28.4) 62.35,28.55 C39.1@62.95,28.55 ; C39.1@63,28.71 C39.1@63.05,28.76 ; C140.2@70.9,24.16 71.56,24.16 v2(71.6,24.2) ; v2(78.9,16.7) 79.14,16.94 C103.2@79.6,16.94 ; C102.2@80.6,16.94 80.6,16.475 v2(80.8,16.275) ; R226.1@90.8,16.9 90.9,16.8 v3(91.7,16.8)
  Bottom w0.4: R38.2@66.2,38.68 66.857,38.68 v3(67.183,38.354) ; v3(84.3,44.6) 84.9,45.2 85.7,45.2 85.79,45.11 J14.14@86.49,45.11
  Bottom w0.5: v1(59.4,34.8) 59.45,34.85 J12.21@60.85,34.85
  other v1: 6,0.805 7,0.805 8,0.805 9,0.805 10,0.805 11,0.805 12,0.805 13,0.805 14,0.805 15,0.805 16,0.805 17,0.805 18,0.805 19,0.805 20,0.805 21,0.805 22,0.805 23,0.805 24,0.805 25,0.805 26,0.805 27,0.805 28,0.805 29,0.805 30,0.805 31,0.805 32,0.805 33,0.805 34,0.805 35,0.805 36,0.805 37,0.805 38,0.805 39,0.805 40,0.805 41,0.805 42,0.805 43,0.805 44,0.805 45,0.805 59,0.805 60,0.805 61,0.805 62,0.805 69,0.805 70,0.805 71,0.805 72,0.805 73,0.805 74,0.805 75,0.805 76,0.805 77,0.805 78,0.805 79,0.805 83,0.805 84,0.805 87,0.805 88,0.805 89,0.805 90,0.805 91,0.805 92,0.805 93,0.805 94,0.805 70.275,3.75 0.805,6 99.195,6 0.805,7 99.195,7 54.25,7.5 61.9,7.8 0.805,8 99.195,8 0.805,9 99.195,9 15.25,9.5 33.5,9.5 0.805,10 99.195,10 61.8,10.6 67.225,10.9 0.805,11 99.195,11 6.8,11.2 4.6,11.3 0.805,12 99.195,12 80.1,12.05 89.8,12.5 90.6,12.5 92,12.5 92.8,12.5 95.75,12.75 0.805,13 4.6,13 99.195,13 6.7,13.1 95.75,13.5 0.805,14 99.195,14 79.5,14.5 87.4,14.6 0.805,15 99.195,15 80.75,15.25 87.304,15.795 95.9,15.9 0.805,16 99.195,16 69.6,16.3 92.4,16.7 93.1,16.7 69.571,16.971 0.805,17 83.7,17 87.3,17 99.195,17 88.3,17.3 0.805,18 99.195,18 95.7,18.5 55.25,18.75 51.6,18.9 0.805,19 99.195,19 23.4,19.2 95.7,19.4 67.75,19.5 84,19.8 0.805,20 76.1,20 99.195,20 79,20.1 58.2,20.3 57,20.5 0.805,21 99.195,21 52.7,21.2 46.75,21.25 44.1,21.3 74.3,21.5 67.953,21.701 36.5,21.75 0.805,22 99.195,22 95,22.2 18.9,22.7 15.5,22.75 37.6,22.8 93.8,22.8 0.805,23 99.195,23 54.323,23.063 40.5,23.25 44,23.25 19.9,23.4 0.805,24 79.3,24 99.195,24 17.3,24.2 50.8,24.2 42,24.5 74.6,24.5 93.5,24.7 76.5,24.8 0.805,25 99.195,25 13.6,25.4 0.805,26 99.195,26 26.2,26.1 21.5,26.2 91.2,26.4 41.25,26.5 96.25,26.75 0.805,27 99.195,27 33.5,27.6 90.4,27.6 0.805,28 35.4,28 99.195,28 29.8,28.3 20.5,28.6 0.805,29 99.195,29 36.75,29.25 96.25,29.25 59.575,29.3 49.7,29.9 54.1,29.9 0.805,30 99.195,30 81.504,30.326 91.2,30.9 0.805,31 35.3,31 96.25,31 59.5,31.6 17.5,31.7 0.805,32 99.1,32 59.5,32.4 97,32.5 49.7,32.8 99.15,32.825 0.805,33 95,33.5 20.8,33.7 0.805,34 33.25,34 34.5,34 99.195,34.475 54.3,34.6 35,34.7 0.805,35 89.704,35.077 92.2,35.1 58,35.5 96.4,35.9 97.4,35.9 0.805,36 46,36.75 12.7,36.8 26.9,36.8 99.175,36.875 0.805,37 87.815,37.63 0.805,38 47.5,38 88.9,38.1 89.7,38.1 90.5,38.1 87.175,38.25 86.545,38.9 0.805,39 49.25,39 50.5,39 54.5,39 55.75,39 87.2,39.55 88.9,39.7 89.7,39.7 33.9,39.8 90.5,39.8 0.805,40 87.815,40.17 18.1,40.2 19.1,40.2 59.4,40.4 0.805,41 58.157,41.935 0.805,42 99.195,42 96.5,42.1 97.1,42.1 45.25,42.75 90.5,42.75 0.805,43 6.5,43 21.4,43 99.195,43 59.3,43.05 0.805,44 99.195,44 37.9,44.9 51.2,44.9 0.805,45 99.195,45.9 0.805,46 21.1,46 23.7,46 41.617,46.04 25.5,46.1 99.195,46.9 0.805,47 23.7,47.9 25.6,47.9 0.805,48 99.195,48 92.489,48.398 0.805,49 99.195,49 15.8,49.2 37.4,49.2 5.1,49.7 0.805,50 99.195,50 35.1,50.1 55.2,50.7 0.805,51 99.195,51 93.052,51.148 49.5,51.2 51,51.4 54.3,51.6 0.805,52 99.195,52 54.15,52.55 52.5,52.7 0.805,53 99.195,53 60.9,53.5 0.805,54 99.195,54 0.805,55 99.195,55 7.6,55.5 84,55.5 86.5,55.6 0.805,56 99.195,56 0.805,57 99.195,57 64.4,57.7 65.5,57.7 0.805,58 70.7,58 99.195,58 55.4,58.2 52.6,58.3 83.6,58.3 80.6,58.4 0.805,59 99.195,59 56.6,59.1 77.4,59.1 83.7,59.8 0.805,60 99.195,60 15.3,60.1 0.805,61 99.195,61 87.4,61.6 9.3,61.8 0.805,62 92.75,62 99.195,62 77.4,62.8 0.805,63 22.5,63 25.8,63 99.195,63 10.3,63.4 72.5,63.7 18.75,63.75 0.805,64 15.1,64 99.195,64 79.75,64.5 0.805,65 99.195,65 0.805,66 99.195,66 33.6,66.8 21.2,68.8 19.475,68.825 41,71.175 6,71.195 7,71.195 14,71.195 15,71.195 16,71.195 17,71.195 18,71.195 19,71.195 20,71.195 21,71.195 22,71.195 23,71.195 24,71.195 25,71.195 26,71.195 27,71.195 28,71.195 29,71.195 30,71.195 31,71.195 32,71.195 33,71.195 36,71.195 39,71.195 40,71.195 42,71.195 43,71.195 44,71.195 45,71.195 46,71.195 49,71.195 50,71.195 51,71.195 52,71.195 53,71.195 54,71.195 55,71.195 56,71.195 57,71.195 58,71.195 62,71.195 63,71.195 64,71.195 65,71.195 66,71.195 67,71.195 68,71.195 69,71.195 70,71.195 71,71.195 72,71.195 73,71.195 74,71.195 75,71.195 76,71.195 77,71.195 78,71.195 79,71.195 80,71.195 81,71.195 82,71.195 83,71.195 84,71.195 85,71.195 86,71.195 87,71.195 88,71.195 89,71.195 90,71.195 91,71.195 92,71.195 93,71.195 94,71.195
  other v2: 77.7,3.9 77.7,6.5 76.4,6.6 79.6,6.7 72.75,6.75 75,7.25 76.4,8.4 77.6,8.4 70.5,9.25 71.5,9.25 75,9.5 76.25,10.25 72.9,10.3 74,10.5 77.6,10.6 70.25,12 71.75,12 73,12 76.6,12.1 75,12.25 78,12.5 76.625,13.8 75.325,13.825 75,16.025 51.6,16.1 75.4,16.3 70.2,18.2 71.5,18.2 80.4,19.2 70.2,21.5 20.6,23.2 28.6,23.2 22.6,25 24.3,25 25.5,25 38.9,25.1 40.2,25.1 28.7,25.2 38.6,25.6 23,27.3 25,27.3 86.5,28.2 23,29.1 25,29.2 39.6,32.1 41.3,32.1 42.9,32.1 26.6,33.6 22,33.7 42.9,33.8 39.6,34.1 42.9,35.4 50,36.675 95.461,37.4 28.93,37.63 92.93,37.827 93.78,37.902 25.5,38.95 26.075,38.95 93.6,39.7 92.2,39.8 23.2,40 95.4,40.6 40,41.25 41,41.25 33.2,41.5 37.1,41.6 42.5,41.75 38.9,41.8 25.5,41.95 26.175,41.975 28.2,42.6 55.8,42.725 48.5,43 47.4,43.6 47.4,45 46.9,47.2 29.5,47.7 18,49.8 21.1,50 48.8,50.5 59.4,50.5 19.4,50.8 48.8,51.2 21.6,52.5 37.9,52.6 27.095,52.85 7.7,52.9 15.5,55 21.7,55 47.25,55.05 68.025,55.525 88.597,55.904 79.4,56.6 7.6,56.7 87.4,57.4 21.325,57.475 20.2,57.6 19.2,57.7 67.7,58.3 94.2,58.6 48.7,58.9 12.725,59.25 13.825,59.25 15.6,59.5 48.7,59.8 18.2,60 26.9,60.4 19.575,60.45 21.975,60.475 74.575,60.48 60.1,60.6 23.369,60.833 29.325,60.95 25.65,61.125 74.325,61.775 48,63.6 45.775,63.975 39.475,66.8 52.475,68.55 54.825,68.875 57.1,68.925 53.8,69.6
  other v3: 55.3,16.2 84.2,23.1 84.8,23.1 22.7,23.2 76.2,29.5 82.677,31.496 70,31.6 83.947,31.877 67.437,32.131 67.183,33.147 84.328,33.147 67.183,34.417 84.328,34.417 67.183,35.687 84.328,35.687 84.328,36.957 67.183,37.084 84.328,38.227 84.328,39.497 84.328,40.767 67.225,40.825 84.328,42.037 67.183,42.164 67.183,43.434 67.2,44.5 84.328,45.847 67.2,46 84.328,47.117 67.183,47.244 84.328,48.387 67.183,48.514 84.328,49.657 67.183,49.784 67.5,50.8 84.074,50.8 68.846,51.296 70.104,51.308 71.374,51.308 72.644,51.308 73.914,51.308 75.184,51.308 76.454,51.308 77.724,51.308 78.994,51.308 80.264,51.308 81.534,51.308 82.804,51.308
GPS_COEX: J13.10 U11.C14 | length 27
  Top w0.125: U11.C14@85.91,37.63 v1(86.545,36.995)
  Signal_3 w0.125: v2(94.5,43.25) 94.5,49 95.1,49.6 95.1,51.676 96.424,53 J13.10@97.75,53
  Signal_7 w0.125: v1(86.545,36.995) 88.295,36.995 88.85,37.55 91.825,37.55 92,37.375 94.075,37.375 94.528,37.828 94.528,40.085 94.08,40.532 94.08,42.83 v2(94.5,43.25)
I2C1_SCL: R95.1 R103.1 R106.1 R108.1 R109.1 R114.1 R187.1 R199.1 R274.2 U36.6 | length 10.9
  Top w0.119: R274.2@58.98,24.4 58.98,23.82 59.18,23.62 U36.6@59.18,23.4 60.17,23.4 R199.1@60.25,23.48 R187.1@61.5,23.48 R95.1@62.75,23.48 R103.1@64,23.48 R106.1@65.25,23.48 R108.1@66.5,23.48 R114.1@67.75,23.48 R109.1@69,23.48
I2C1_SDA: R96.1 R105.1 R107.1 R110.1 R111.1 R115.1 R188.1 R200.1 R275.2 U36.3 | length 14.8
  Top w0.119: R275.2@57.82,21.4 57.82,21.88 57.62,22.08 U36.3@57.62,22.4 v2(58.2,22.4) ; v2(59.3,25.2) 59.73,24.77 R200.1@60.25,24.77 R188.1@61.5,24.77 R96.1@62.75,24.77 R105.1@64,24.77 R107.1@65.25,24.77 R111.1@66.5,24.77 R115.1@67.75,24.77 R110.1@69,24.77
  Signal_3 w0.127: v2(58.2,22.4) 58.2,23.5 59.3,24.6 v2(59.3,25.2)
INTERNAL_I2C1_SCL: R274.1 U11.Y7 U36.1 | length 29.2
  Top w0.119: U36.1@57.62,23.4 57.8,23.4 58.02,23.62 R274.1@58.02,24.4 58.02,24.965 58.02,25.08 58.1,25 v2(58.1,25.1) ; v1(63.685,47.155) U11.Y7@64.32,46.52
  Signal_8 w0.127: v2(58.1,25.1) 58.1,27.334 58.67,27.905 58.67,28.276 59.12,28.726 59.12,29.074 59.104,29.09 59.104,29.495 60,30.39 60,36.585 59.529,37.055 59.529,39.479 60.3,40.25 60.3,46.1 60.885,46.685 63.215,46.685 v1(63.685,47.155)
INTERNAL_I2C1_SDA: R275.1 U11.Y8 U36.4 | length 29.8
  Top w0.119: U36.4@59.18,22.4 59,22.4 58.78,22.18 R275.1@58.78,21.4 v2(59.6,21.4) ; v1(63.7,45.9) 63.67,45.9 U11.Y8@64.32,45.25
  Signal_8 w0.127: v2(59.6,21.4) 59.679,21.479 60.274,21.479 60.52,21.726 60.52,22.42 63.2,25.1 63.2,32.834 63.029,33.005 63.029,35.414 63.12,35.505 63.12,35.895 63.03,35.986 63.03,45.23 v1(63.7,45.9)
IOEXP_3: J30.1 U27.6 | length 61.4
  Top w0.119: J30.1@2,27.25 2.733,27.25 3.484,28 3.484,29.227 3.384,29.327 3.384,29.673 3.627,29.916 3.958,29.916 4.362,30.321 4.362,30.983 v2(3.912,31.433) ; v1(51.4,38.1) 51.43,38.069 51.43,37.705 52.25,36.886 U27.6@52.25,35.7
  Signal_3 w0.127: v2(3.912,31.433) 4.098,31.618 6.458,31.618 6.852,32.012 9.466,32.012 10.116,31.362 14.117,31.362 16,33.245 16.31,33.245 16.572,33.506 16.572,33.585 17.195,34.208 18.61,34.208 19.723,33.096 25.501,33.096 27.28,34.874 28.099,34.874 29.014,35.79 30.558,35.79 31.518,36.75 32.991,36.75 33.262,36.478 41.901,36.478 42.897,37.474 46.3,37.474 46.53,37.244 47.84,37.244 48.305,36.779 48.82,36.779 49.55,37.509 50.509,37.509 51.1,38.1 v1(51.4,38.1)
IOEXP_4: J30.3 U27.7 | length 57.3
  Top w0.119: J30.3@2,29.75 2.704,29.75 2.954,30 2.954,30.254 3.3,30.6 v2(3.7,30.6) ; v1(51.217,37.255) 51.495,37.255 51.75,37 U27.7@51.75,35.7
  Signal_3 w0.127: v2(3.7,30.6) 3.8,30.6 4.564,31.364 6.563,31.364 6.957,31.758 9.361,31.758 10.011,31.108 14.222,31.108 14.687,31.573 15.689,31.573 16.826,32.709 16.826,33.479 17.3,33.954 18.505,33.954 19.618,32.842 25.606,32.842 25.944,33.179 26.774,33.179 27.02,33.426 27.02,34.12 27.521,34.62 28.204,34.62 29.119,35.536 30.663,35.536 30.932,35.805 32.11,35.805 32.53,36.224 42.006,36.224 43.002,37.22 46.195,37.22 46.425,36.99 47.735,36.99 48.2,36.525 48.926,36.525 49.655,37.255 v1(51.217,37.255)
IOEXP_5: J30.4 U27.8 | length 55.8
  Top w0.119: v1(51.2,36.5) 51.2,35.75 U27.8@51.25,35.7
  Signal_3 w0.127: J30.4@2,31 3,31 3.279,30.721 3.279,30.426 3.526,30.179 3.874,30.179 4.805,31.11 6.668,31.11 7.062,31.504 9.255,31.504 9.905,30.854 14.361,30.854 14.826,31.319 15.794,31.319 17.08,32.604 17.08,33.374 17.405,33.7 18.4,33.7 19.52,32.58 25.455,32.58 25.883,32.152 26.88,32.152 30.009,35.282 30.768,35.282 30.987,35.5 31.705,35.5 32.204,35 34.135,35 35.105,35.97 42.311,35.97 42.545,36.204 50.904,36.204 v1(51.2,36.5)
IOEXP_6: J30.2 U27.13 | length 62.8
  Top w0.119: J30.2@2,28.5 2.9,28.5 3.238,28.838 3.238,29.126 3.138,29.226 3.138,29.774 3.547,30.183 3.873,30.183 4.116,30.427 4.116,30.772 3.873,31.016 3.74,31.016 3.496,31.26 3.496,31.605 3.5,31.609 v2(3.5,31.9) ; U27.13@48.55,35 48,35 47.91,35.09 47.91,37.324 48.625,38.038 48.625,39.146 49.28,39.802 v2(49.28,39.987)
  Signal_3 w0.127: v2(3.5,31.9) 3.75,31.9 3.778,31.872 6.353,31.872 7.731,33.25 9.095,33.25 9.504,32.841 9.504,32.692 10.296,31.9 13.936,31.9 14.371,32.335 14.371,33.671 15.625,34.925 19.041,34.925 19.824,35.708 23.41,35.708 23.728,36.026 26.791,36.026 27.319,36.554 30.219,36.554 31.215,37.55 34.687,37.55 35.537,38.4 43.899,38.4 43.97,38.329 45.586,38.329 47.244,39.987 v2(49.28,39.987)
IOEXP_37: R89.1 U27.47 | length 47.7
  Top w0.119: v2(17.4,30.8) 17.764,30.436 R89.1@19.82,30.436 ; U27.47@55.45,34.5 56.8,34.5 v2(56.9,34.6)
  Signal_3 w0.127: v2(17.4,30.8) 18.2,30.8 19.726,32.326 25.35,32.326 25.876,31.8 26.89,31.8 28.616,33.526 29.126,33.526 29.4,33.8 30.672,33.8 31.272,33.2 36.246,33.2 37.221,34.174 37.474,34.174 37.5,34.2 38.6,34.2 39.2,33.6 41.746,33.6 42.396,34.25 43.1,34.25 43.75,33.6 45.172,33.6 45.872,34.3 49.778,34.3 50.028,34.05 53.071,34.05 53.5,33.621 55.621,33.621 56.6,34.6 v2(56.9,34.6)
IOEXP_I2C0_SCL: R187.2 U27.29 | length 20.2
  Top w0.119: v1(50.9,27.2) 50.9,27.1 51,27 51.267,27.267 51.267,28.783 U27.29@51.25,28.8 ; v2(61.5,22) R187.2@61.5,22.52
  Signal_3 w0.127: v1(50.9,27.2) 52.968,25.132 52.968,22.675 53.932,21.71 53.932,20.782 54.986,19.729 55.655,19.729 56.37,19.013 59.013,19.013 61.5,21.5 v2(61.5,22)
IOEXP_I2C0_SDA: R188.2 U27.30 | length 16.9
  Top w0.119: U27.30@51.75,28.8 51.75,25.75 53.75,23.75 v1(54.273,23.75) ; R188.2@61.5,25.73 61.5,26.295 61.605,26.4 v2(62.3,26.4)
  Signal_7 w0.127: v1(54.273,23.75) 55.385,23.75 55.655,24.021 59.92,24.021 v2@62.3,26.4
IOEXP_INT_IMX#: R254.2 R283.2 U27.46 | length 3.4
  Top w0.127: U27.46@55.45,34 55.522,34.072 56.63,34.072 56.702,34 57.52,34 R254.2@57.6,34.08 R283.2@58.8,34.08
IOEXP_INT_MCA#: R262.1 U11.A2 U27.25 | length 83
  Top w0.119: U11.A2@88.45,52.87 v1(89.3,52.87)
  Top w0.127: v1(46.5,26.8) 48.18,26.8 48.4,26.58 R262.1@49.2,26.58 49.25,26.63 U27.25@49.25,28.8
  Signal_3 w0.119: v1(43.25,46.3) 43.382,46.432 48.634,46.432 49.143,45.923 52.672,45.923 58.048,51.3 59.981,51.3 60.402,50.88 60.998,50.88 61.419,51.3 62.14,51.3 62.207,51.366 63.316,51.366 64.675,52.725 65.625,52.725 65.9,53 66.9,53 67.5,53.6 68.944,53.6 69.316,53.971 71.221,53.971 71.95,54.7 71.95,55.15 72.55,55.75 74.572,55.75 74.696,55.874 75.503,55.874 75.628,55.75 80.95,55.75 82.066,56.866 88.934,56.866 89.95,55.85 89.95,53.52 v1(89.3,52.87)
  Signal_8 w0.127: v1(43.25,46.3) 44.25,45.3 44.25,41.1 46.55,38.8 46.55,28.528 46.987,28.091 46.987,27.287 v1(46.5,26.8)
IOEXP_RESET_N: CAD3.10 J37.10 R257.2 U27.26 | length 62.2
  Top w0.119: v1(7.7,41.6) R257.2@8.3,41.6 ; v1(13,29.25) 13,30.992 J37.10@13.04,31.032 13.202,31.194 13.202,33.857 v2@13.345,34 ; v2(13.3,34) v2@13.345,34 ; v2@13.372,34.028 v2@13.345,34 ; v1(49.75,28) U27.26@49.75,28.8
  Signal_7 w0.127: v1(7.7,41.6) 7.7,40.1 8.25,39.55 8.25,38.038 11.288,35 12.4,35 13.3,34.1 v2(13.3,34) 13.3,33.985 13.372,33.913 13.43,33.97 14.338,33.97 14.778,34.41 16.456,34.41 16.465,34.4 19.445,34.4 19.515,34.471 20.155,34.471 20.455,34.171 20.978,34.171 21.726,34.919 23.242,34.919 24.981,33.179 26.774,33.179 27.02,33.426 27.02,33.874 28.592,35.445 31.481,35.445 31.727,35.199 31.727,34.181 31.675,34.129 31.675,33.571 32.155,33.091 32.155,32.6 33.28,31.476 33.28,30.926 36.113,28.092 45.208,28.092 45.975,27.325 49.075,27.325 v1(49.75,28)
  Bottom w0.119: v1(13,29.25) 13.04,29.21 CAD3.10@13.04,28.385
IOEXP_SWD_CLK/LVDS_FLIP: CAD3.4 J37.4 R249.1 U27.17 | length 74.1
  Top w0.119: v2(9,32.75) 9,31.262 J37.4@9.23,31.032 9.23,29.27 v2(9.25,29.25) ; v3(36.7,52.5) R249.1@36.7,53.42 ; v2(37.1,37.153) 37.753,36.5 40,36.5 41.75,38.25 46.284,38.25 46.436,38.097 46.436,37.591 46.75,37.278 46.75,34.066 47.816,33 U27.17@48.55,33
  Signal_3 w0.127: v2(9,32.75) 9.087,32.75 10.221,31.616 14.012,31.616 14.7,32.304 14.7,33.525 15.775,34.6 19.075,34.6 19.929,35.454 23.554,35.454 23.854,35.754 26.879,35.754 27.422,36.298 30.322,36.298 31.321,37.296 33.163,37.296 33.306,37.153 v2(37.1,37.153)
  Signal_8 w0.127: v3(36.7,52.5) 37.6,51.6 37.6,50.4 39,49 39,47.735 37.25,45.985 37.25,44.884 37.453,44.682 37.453,43.5 36.679,42.727 36.679,41.426 37.17,40.935 37.17,36.971 37.1,37.041 v2(37.1,37.153)
  Bottom w0.119: CAD3.4@9.23,27.115 8.54,27.805 8.54,29.04 8.75,29.25 v2(9.25,29.25)
IOEXP_SWD_DIO/LVDS_RF: CAD3.2 J37.2 R248.1 U27.20 | length 85
  Top w0.119: v2(7.325,30.25) 7.91,30.25 7.96,30.3 J37.2@7.96,31.032 ; v2(47.35,31.575) 47.425,31.5 U27.20@48.55,31.5
  Signal_3 w0.127: v2(14.5,25.5) 14.628,25.372 16.728,25.372 17.119,25.762 19.012,25.762 20.175,26.925 22.781,26.925 22.826,26.879 23.985,26.879 24.826,27.72 27.793,27.72 27.985,27.528 32.388,27.528 33.184,28.325 33.8,28.325 34.725,27.4 35.463,27.4 35.593,27.529 35.595,27.529 35.87,27.805 35.87,27.807 35.979,27.916 39.065,27.916 40.903,29.754 44.151,29.754 45.123,30.726 46.501,30.726 v2(47.35,31.575)
  Signal_8 w0.127: v2(46.8,63.8) 47.3,63.3 47.3,58.646 46.2,57.545 46.2,50.8 44.78,49.38 44.78,44.68 44.904,44.555 44.904,44.345 44.526,43.966 44.526,41.184 46.804,38.905 46.804,32.121 v2(47.35,31.575)
  Bottom w0.119: v2(7.325,30.25) 10.411,30.25 11.19,29.472 11.19,27.695 CAD3.2@11.77,27.115 12.896,25.989 14.011,25.989 v2(14.5,25.5) ; v2(46.8,63.8) 46.8,62.98 R248.1@46.88,62.9
IOEXP_UART2_RX: U9.17 U27.4 | length 26.7
  Top w0.119: U9.17@30.15,35.025 v2(31.307,35.025) ; U27.4@53.25,35.7 53.25,36.575 v1(53.425,36.75)
  Signal_3 w0.127: v2(31.307,35.025) 31.732,34.6 33.675,34.6 33.974,34.3 33.974,33.826 34.3,33.5 35.75,33.5 37.95,35.7 42.4,35.7 42.65,35.95 52.625,35.95 v1(53.425,36.75)
IOEXP_UART2_TX: U9.12 U27.3 | length 41.6
  Top w0.119: v1(20.674,34.826) 21.077,35.229 22.083,35.229 22.287,35.025 U9.12@24.35,35.025 ; v1(53.7,37.7) 53.8,37.7 53.895,37.605 53.895,36.556 53.75,36.411 U27.3@53.75,35.7
  Signal_3 w0.127: v1(20.674,34.826) 21.048,35.2 23.7,35.2 24,35.5 26.984,35.5 27.527,36.044 30.427,36.044 31.426,37.042 33.058,37.042 33.368,36.732 37.05,36.732 41.796,36.732 42.792,37.728 46.405,37.728 46.604,37.529 48.054,37.529 48.325,37.8 50.325,37.8 51.264,38.739 51.767,38.739 52.807,37.7 v1(53.7,37.7)
JTAG_MOD: R37.2 U11.AA15 | length 6.5
  Top w0.119: v1(62.65,35.7) 62.65,35.96 U11.AA15@63.05,36.36
  Bottom w0.119: v1(62.65,35.7) 63.35,36.4 64.05,36.4 64.25,36.6 R37.2@64.25,40.27
JTAG_TCK/SAI2_RX_DATA: CAD1.4 R191.1 U11.W21 | length 130.8
  Top w0.119: v2(59.493,28.496) 60.904,28.496 61.9,27.5 64.35,27.5 64.898,28.048 v2(64.898,28.588) 64.91,28.588 65.002,28.496 65.246,28.74 U11.W21@65.59,28.74
  Signal_3 w0.127: v3(14.236,30.415) 15.915,30.415 15.951,30.379 18.139,30.379 19.832,32.072 25.245,32.072 25.771,31.546 26.995,31.546 28.721,33.272 29.232,33.272 29.454,33.494 30.459,33.494 31.008,32.946 36.351,32.946 37.326,33.92 38.393,33.92 38.967,33.346 45.278,33.346 45.957,34.025 49.693,34.025 49.922,33.796 52.863,33.796 55.754,30.905 55.754,30.055 56.681,29.128 56.681,29.126 56.926,28.881 58.086,28.881 58.526,29.321 58.874,29.321 59.493,28.702 v2(59.493,28.496)
  Signal_8 w0.127: v1(13.4,35.6) 12.1,35.6 11.25,34.75 11.25,31.95 12.95,30.25 14.071,30.25 v3(14.236,30.415) ; v2(64.898,28.588) 64.646,28.335 64.646,25.468 61.92,22.743 61.92,21.68 60.546,20.305 60.546,18.705 59.754,17.913 59.754,16.348 61.174,14.928 61.174,12.772 60.746,12.344 60.746,9.676 61.174,9.248 61.174,5.726 62.221,4.679 63.986,4.679 64.007,4.7 66.3,4.7 68.7,7.1 68.7,12.391 68.146,12.945 68.146,15 68.751,15.605 69.099,15.605 69.244,15.46 69.956,15.46 73.75,19.254 79.2,19.254 79.821,19.874 81.46,19.874 81.805,19.53 82.73,19.53 v1(83.2,20)
  Bottom w0.119: CAD1.4@11.885,35.98 13.02,35.98 v1(13.4,35.6) ; v1(83.2,20) R191.1@83.2,20.72
JTAG_TDI/SAI2_TX_BCLK: CAD1.8 R131.1 U11.V21 | length 132.8
  Top w0.119: v1(66.16,28.17) 66.29,28.17 U11.V21@66.86,28.74
  Signal_3 w0.127: v1(9,35.75) 12.55,35.75 13.1,36.3 16.79,36.3 17.115,36.624 18.525,36.624 18.9,36.25 23.234,36.25 24.254,37.27 26.2,37.27 27.234,38.304 34.723,38.304 35.419,39.001 43.69,39.001 44.43,39.74 45.204,39.74 46.046,40.582 48.028,40.582 48.3,40.854 50.371,40.854 52.751,38.475 54.001,38.475 54.454,38.022 55.888,38.022 56.845,38.978 57.655,38.978 58.659,37.974 60.3,37.974 60.724,37.55 60.724,36.679 62.224,35.18 62.715,35.18 63.14,34.755 63.14,34.155 63.37,33.924 63.8,33.924 64.224,33.5 64.224,32.7 63.14,31.615 63.14,28.896 63.355,28.68 63.985,28.68 64.498,28.167 66.157,28.167 v1(66.16,28.17)
  Signal_8 w0.127: v1(66.16,28.17) 66.11,28.22 65.126,28.22 65.072,28.167 65.067,28.167 64.9,28 64.9,25.363 62.262,22.725 62.262,21.662 60.8,20.2 60.8,18.6 60.008,17.808 60.008,16.453 61.428,15.034 61.428,12.666 61,12.239 61,9.781 61.428,9.354 61.428,6.846 62.344,5.929 65.429,5.929 68.4,8.9 68.4,12.25 67.75,12.9 67.75,16.65 70.608,19.508 79.095,19.508 79.715,20.128 81.872,20.128 v1(82,20)
  Bottom w0.119: v1(9,35.75) 9,36.25 10,37.25 CAD1.8@10.615,37.25 ; v1(82,20) R131.1@82,20.77
JTAG_TDO/SAI2_TX_SYNC: CAD1.6 R189.1 U11.Y21 | length 132.3
  Top w0.119: v1(63.79,28.21) U11.Y21@64.32,28.74
  Signal_3 w0.127: v1(9.2,34.7) 9.219,34.7 9.773,35.254 13.081,35.254 13.205,35.129 13.595,35.129 13.719,35.254 16.554,35.254 17.671,36.37 18.42,36.37 18.794,35.996 23.339,35.996 23.623,36.28 25.818,36.28 26.093,36.555 26.093,36.693 27.45,38.05 34.828,38.05 35.524,38.747 43.795,38.747 44.535,39.486 45.309,39.486 46.151,40.328 48.133,40.328 48.405,40.6 50.266,40.6 52.646,38.221 53.896,38.221 54.349,37.768 55.993,37.768 56.95,38.724 57.55,38.724 58.554,37.72 60.195,37.72 60.47,37.445 60.47,36.433 61.978,34.926 62.61,34.926 62.886,34.65 62.886,34.05 63.265,33.67 63.695,33.67 63.97,33.395 63.97,32.805 62.886,31.72 62.886,28.414 63.09,28.21 v1(63.79,28.21)
  Signal_8 w0.127: v1(63.79,28.21) 63.79,25.331 60.774,22.315 60.774,21.252 60.038,20.516 60.038,18.916 59.192,18.07 59.192,16.191 60.666,14.718 60.666,12.982 60.238,12.555 60.238,9.465 60.666,9.038 60.666,4.775 63.341,2.1 64.85,2.1 66.079,3.329 66.079,3.674 69.3,6.895 69.3,13.605 69.28,13.626 69.28,14.48 69.752,14.952 70.166,14.952 72.614,17.4 75.705,17.4 76.026,17.721 76.04,17.721 76.92,18.6 79.505,18.6 80.026,18.08 80.52,18.08 v1(81.6,17)
  Bottom w0.119: v1(9.2,34.7) 9.21,34.71 CAD1.6@10.615,34.71 ; v1(81.6,17) 81.6,17.71 R189.1@81.66,17.77
JTAG_TMS/SAI2_MCLK: CAD1.2 R94.1 U11.AA16 | length 97
  Top w0.119: v1(62.415,34.455) U11.AA16@63.05,35.09
  Signal_3 w0.127: v1(13.73,38.02) 14.714,39.004 21.504,39.004 22.92,40.42 26.828,40.42 27.659,41.252 29.309,41.252 31.232,39.329 34.83,39.329 v2(36,40.5)
  Signal_7 w0.127: v2(36,40.5) 36.3,40.2 37.387,40.2 37.79,40.604 38.974,40.604 43.023,36.555 45.529,36.555 46.309,35.775 52.085,35.775 52.701,36.391 52.701,37.05 52.954,37.304 52.954,37.979 53.501,38.525 55.941,38.525 56.648,39.232 58.071,39.232 58.649,38.654 59.621,38.654 60.724,37.55 60.724,37.076 61.945,35.856 61.945,34.926 v1(62.415,34.455) 62.91,34.455 63.977,33.389 63.977,33.123 64.61,32.49 65.27,32.49 65.472,32.288 65.472,31.644 66,31.116 66.42,31.116 68.38,29.156 68.38,29.126 68.626,28.88 69.079,28.88 69.22,29.021 69.22,30.62 69.781,31.181 70.541,31.181 71.11,31.751 71.5,31.751 72.039,31.211 72.039,30.366 72.38,30.024 72.77,30.024 73.607,30.862 74.896,30.862 74.905,30.87 76.129,30.87 76.19,30.81 77.185,30.81 77.275,30.9 78.025,30.9 78.295,31.17 78.995,31.17 79.195,30.97 79.665,30.97 79.906,30.729 80.484,30.729 80.554,30.8 81.835,30.8 82.105,31.07 82.73,31.07 83.33,30.471 83.33,29.695 83.329,29.305 83.8,28.834 83.8,25.2 v1(84.5,24.5)
  Bottom w0.119: CAD1.2@11.885,38.52 12.385,38.02 v1(13.73,38.02) ; R94.1@83.68,24.5 v1(84.5,24.5)
JTAG_TRST_N/SAI2_TX_DATA: CAD1.9 R36.1 R190.1 U11.U21 | length 151.2
  Top w0.119: v1(6.5,36.9) 6.5,36.3 7.02,35.78 R36.1@7.7,35.78 ; v1(67.495,28.105) U11.U21@68.13,28.74
  Signal_3 w0.127: v1(6.5,36.9) 7.59,36.9 7.99,36.5 11.466,36.5 12.401,37.435 14.1,37.435 15.415,38.75 21.784,38.75 22.305,38.229 22.804,38.229 24.572,39.997 27.737,39.997 28.284,39.45 28.562,39.45 28.937,39.075 35.135,39.075 35.314,39.255 43.585,39.255 44.324,39.994 45.099,39.994 45.94,40.836 47.923,40.836 48.195,41.108 50.476,41.108 52.805,38.779 54.055,38.779 54.559,38.276 55.782,38.276 56.739,39.232 57.761,39.232 58.765,38.228 60.405,38.228 60.979,37.655 60.979,37.225 61.954,36.25 63.825,36.25 64.415,35.661 64.415,33.669 64.478,33.605 64.478,32.503 64.231,32.255 64.231,30.345 63.886,30 63.546,30 63.394,29.847 63.394,29.406 63.792,29.008 65.927,29.008 66.235,28.7 66.9,28.7 v1(67.495,28.105)
  Signal_8 w0.127: v1(67.495,28.105) 66.9,28.7 65.38,28.7 65.072,29.008 64.724,29.008 64.392,28.676 64.392,25.574 61.028,22.21 61.028,21.147 60.292,20.41 60.292,18.81 59.5,18.018 59.5,16.243 60.92,14.823 60.92,12.877 60.492,12.449 60.492,9.571 60.92,9.143 60.92,4.88 62.4,3.4 65.4,3.4 69,7 69,12.45 68.4,13.05 68.4,14.895 68.676,15.171 69.024,15.171 69.06,15.206 70.061,15.206 73.055,18.2 75,18.2 75.8,19 79.305,19 79.626,19.32 79.926,19.32 80.226,19.62 81.08,19.62 82.9,17.8 v1(82.9,17)
  Bottom w0.119: v1(6.5,36.9) 8.18,36.9 9.8,38.52 CAD1.9@10.615,38.52 ; v1(82.9,17) 82.9,17.76 R190.1@82.91,17.77
LCD_CLK: J21.27 U11.C21 U25.F9 | length 133.9
  Top w0.119: J21.27@19.976,67.05 19.976,68.276 v1(20.5,68.8) ; v2(39.927,65.978) 40.2,65.705 40.2,63.25 40.95,62.5 U25.F9@40.95,61.75 ; v1@85.435,28.265 U11.C21@85.91,28.74
  Signal_7 w0.127: v1(20.5,68.8) 20.5,69.5 21.21,70.21 35.79,70.21 38.75,67.25 39.62,67.25 39.904,66.965 39.904,66.001 v2(39.927,65.978) 40.322,65.978 40.547,66.203 40.544,66.206 45.641,66.206 47.826,64.02 52.074,64.02 53.12,62.974 53.12,62.531 53.531,62.12 54.355,62.12 54.5,61.975 56.8,61.975 57.224,62.4 57.224,62.999 60.041,65.816 61.013,65.816 61.463,66.266 78.593,66.266 78.813,66.046 83.456,66.046 86.546,62.956 86.546,61.429 87.677,60.298 91.261,60.298 93.447,58.112 93.447,54.998 96.731,51.714 96.731,43.985 98.129,42.587 98.129,35.245 92.6,29.716 92.6,28.7 91.97,28.071 89.81,28.071 89.18,28.7 87.387,28.7 86.92,28.234 86.92,28.026 86.674,27.779 86.02,27.779 v1(85.6,28.2)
